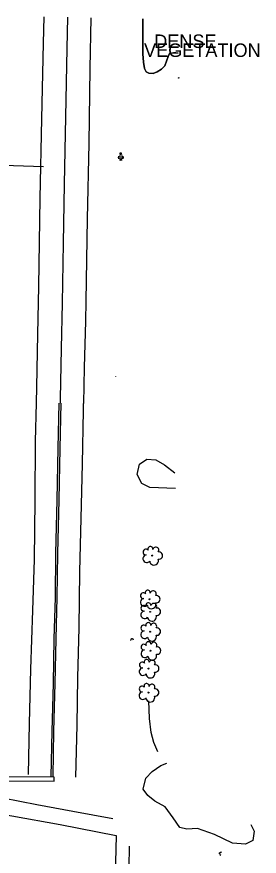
# Model space of a CAD drawing. Extents: x 2129547 to 2134906, y 657330 to 659734.
# Drawn here: x 2132484.8 to 2132610.2, y 659103.9 to 659538.9 of the extents above; entities that cross this region are included whole.
import ezdxf

# ---------------------------------------------------------------- set-up
doc = ezdxf.new("R2010")
doc.units = 0
for name, color, linetype in [('Default', 7, 'Continuous'), ('PM_X_CL_Double_Solid', 7, 'Continuous'), ('PM_X_CL_Double_Solid2', 7, 'Continuous'), ('PM_X_Crosswalk2', 7, 'Continuous'), ('PM_X_Lane_Line', 7, 'Continuous'), ('PM_X_Lane_Line2', 7, 'Continuous'), ('PM_X_Stop_Line2', 7, 'Continuous'), ('SN_X_Cantilever_Overhead', 7, 'Continuous'), ('UT_X_Electric_Cells', 7, 'Continuous'), ('UT_X_Misc_Cells', 7, 'Continuous'), ('UT_X_Unknown_Cells', 7, 'Continuous'), ('VG_X_Cells', 7, 'Continuous'), ('VG_X_Shrub_Line_Lt', 7, 'Continuous'), ('VG_X_Text', 7, 'Continuous'), ('VG_X_Tree_Line_Lt', 7, 'Continuous')]:
    doc.layers.add(name, color=color, linetype=linetype)

# ---------------------------------------------------------------- blocks, each defined once
blk = doc.blocks.new('DM')
at = {"layer": 'UT_X_Misc_Cells'}
blk.add_circle((0, 0), 0.00254, dxfattribs=at)
blk.add_arc((0.01016, 0), 0.01016, 90, 270, dxfattribs=at)
blk = doc.blocks.new('TREE')
at = {"layer": 'VG_X_Cells'}
blk.add_circle((0, 0), 0.00305, dxfattribs=at)
for centre, radius, start, end in [((-0.0125, 0.0428), 0.0167, 354.0047, 205.9741), ((0.0232, 0.0359), 0.0197, 323.83, 165.0376), ((-0.0362, -0.0197), 0.0251, 96.1722, 320.5737), ((-0.042, 0.0237), 0.0187, 39.0625, 279.5412), ((0.0439, 0.0005), 0.0243, 259.1453, 101.4596), ((0.012, -0.0331), 0.029, 184.9476, 19.4572)]:
    blk.add_arc(centre, radius, start, end, dxfattribs=at)
blk = doc.blocks.new('POINT_DISPLAY')
at = {"layer": 'Default'}
blk.add_line((0, 0), (0, 0), dxfattribs=at)

msp = doc.modelspace()

# ---------------------------------------------------------------- linework, layer by layer
at = {"layer": 'PM_X_CL_Double_Solid'}
msp.add_lwpolyline([(2132510.93, 659538.66), (2132510.63, 659522.52), (2132509.98, 659487.05), (2132509.34, 659452.23), (2132508.78, 659421.54), (2132508.27, 659390.56), (2132507.81, 659367.06), (2132507.25, 659340.87), (2132507.21, 659338.69)], dxfattribs=at)
at = {"layer": 'PM_X_CL_Double_Solid2'}
for points in [[(2132502.57, 659145.18), (2132503.03, 659168.68), (2132503.7, 659193.36), (2132504.11, 659216.62), (2132504.73, 659238), (2132505.03, 659260.78), (2132505.68, 659288.58), (2132506.27, 659315.28), (2132506.71, 659338.7)], [(2132503.57, 659145.16), (2132504.03, 659168.66), (2132504.7, 659193.34), (2132505.11, 659216.6), (2132505.72, 659237.98), (2132506.03, 659260.76), (2132506.68, 659288.55), (2132507.27, 659315.26), (2132507.71, 659338.68)]]:
    msp.add_lwpolyline(points, dxfattribs=at)
at = {"layer": 'PM_X_Crosswalk2'}
for points in [[(2132534.55, 659123.31), (2132513.69, 659127.04), (2132495.2, 659130.51), (2132477.48, 659133.95), (2132465.32, 659136.32)], [(2132469.3, 659081.92), (2132465.27, 659103.71), (2132460.59, 659128.44), (2132482.25, 659124.89), (2132507.25, 659120.29), (2132536.23, 659114.67), (2132535.64, 659093.84), (2132534.49, 659067.12), (2132533.02, 659033.77)], [(2132540.65, 659045.1), (2132541.37, 659064.12), (2132542.08, 659085.02), (2132542.85, 659098.09), (2132543.17, 659109.18)]]:
    msp.add_lwpolyline(points, dxfattribs=at)
at = {"layer": 'PM_X_Lane_Line'}
for points in [[(2132494.92, 659338.94), (2132495.11, 659346.96), (2132495.66, 659374.51), (2132496.16, 659399.15), (2132496.9, 659444.94), (2132497.82, 659486.1), (2132498.58, 659525.26), (2132498.94, 659538.9)], [(2132523.05, 659538.41), (2132522.63, 659512.16), (2132522.02, 659473.31), (2132521.15, 659434.29), (2132520.5, 659391.49), (2132520.3, 659381.16), (2132519.61, 659357.21), (2132519.32, 659338.44)]]:
    msp.add_lwpolyline(points, dxfattribs=at)
at = {"layer": 'PM_X_Lane_Line2'}
for points in [[(2132490.82, 659146.24), (2132491.44, 659172.61), (2132492.12, 659200.93), (2132493.01, 659231.29), (2132493.98, 659257.64), (2132494.29, 659288.48), (2132494.43, 659318.87), (2132494.92, 659338.94)], [(2132515.41, 659144.87), (2132516.03, 659171.87), (2132516.43, 659196.48), (2132516.99, 659222.22), (2132517.47, 659251.54), (2132518.16, 659278.93), (2132518.8, 659307.18), (2132519.26, 659334.82), (2132519.32, 659338.44)]]:
    msp.add_lwpolyline(points, dxfattribs=at)
at = {"layer": 'PM_X_Stop_Line2'}
msp.add_lwpolyline([(2132468.48, 659143.04), (2132504.1, 659142.84), (2132504.11, 659144.81), (2132468.49, 659145.01)], close=True, dxfattribs=at)
at = {"layer": 'SN_X_Cantilever_Overhead'}
msp.add_line((2132477.95, 659462.06), (2132498.68, 659461.4), dxfattribs=at)
at = {"layer": 'UT_X_Electric_Cells'}
for p, q in [((2132568.6, 659507.36), (2132568.52, 659507.06)), ((2132568.58, 659507.3), (2132568.64, 659507.3)), ((2132568.6, 659507.36), (2132568.64, 659507.36))]:
    msp.add_line(p, q, dxfattribs=at)
msp.add_circle((2132568.56, 659507.2), 0.065, dxfattribs=at)
msp.add_arc((2132568.64, 659507.33), 0.0319, 268.8767, 91.1233, dxfattribs=at)
at = {"layer": 'UT_X_Unknown_Cells'}
for p, q in [((2132539.2, 659468.01), (2132537.93, 659468.01)), ((2132538.56, 659467.37), (2132538.56, 659468.64)), ((2132538.02, 659466.83), (2132538.02, 659465.45)), ((2132539.11, 659466.83), (2132539.11, 659465.45)), ((2132535.85, 659352.48), (2132535.79, 659352.48)), ((2132535.79, 659352.43), (2132535.79, 659352.36)), ((2132535.82, 659352.45), (2132535.82, 659352.52)), ((2132535.85, 659352.43), (2132535.85, 659352.36))]:
    msp.add_line(p, q, dxfattribs=at)
for centre, radius, start, end in [((2132538.56, 659465.97), 1.4, 150.0184, 209.9816), ((2132538.56, 659465.97), 1.4, 60.0184, 120.0157), ((2132538.56, 659465.97), 1.4, 239.9843, 299.9816), ((2132538.56, 659465.71), 0.6, 205.1924, 334.8076), ((2132538.56, 659465.97), 1.4, 330.0184, 29.9816), ((2132535.82, 659352.38), 0.07, 150.0184, 209.9816), ((2132535.82, 659352.38), 0.07, 60.0184, 120.0157), ((2132535.82, 659352.37), 0.03, 205.1924, 334.8076), ((2132535.82, 659352.38), 0.07, 239.9843, 299.9816), ((2132535.82, 659352.38), 0.07, 330.0184, 29.9816)]:
    msp.add_arc(centre, radius, start, end, dxfattribs=at)
at = {"layer": 'VG_X_Shrub_Line_Lt'}
msp.add_lwpolyline([(2132557.82, 659157.97), (2132555.63, 659162.93), (2132554.28, 659168.11), (2132553.45, 659175.22), (2132553.09, 659184.52)], dxfattribs=at)
at = {"layer": 'VG_X_Text'}
msp.add_lwpolyline([(2132549.92, 659537.86), (2132549.94, 659529.59), (2132550.05, 659519.7), (2132550.32, 659515.32), (2132550.87, 659512.16), (2132551.64, 659510.35), (2132553.17, 659509.75), (2132555.3, 659509.51), (2132557.44, 659510.4), (2132559.65, 659511.69), (2132561.39, 659513.45), (2132563.11, 659518.24), (2132563.86, 659519.84), (2132565.81, 659520.23), (2132567.04, 659520.29), (2132568.32, 659520.08)], dxfattribs=at)
at = {"layer": 'VG_X_Tree_Line_Lt'}
for points in [[(2132568.32, 659520.08), (2132567.04, 659520.29), (2132565.81, 659520.23), (2132563.86, 659519.84), (2132563.11, 659518.24), (2132561.39, 659513.45), (2132559.65, 659511.69), (2132557.44, 659510.4), (2132555.3, 659509.51), (2132553.17, 659509.75), (2132551.64, 659510.35), (2132550.87, 659512.16), (2132550.32, 659515.32), (2132550.05, 659519.7), (2132549.94, 659529.59), (2132549.92, 659537.86)], [(2132566.92, 659294.5), (2132553.69, 659294.97), (2132549.48, 659296.99), (2132547.05, 659301.77), (2132548.22, 659307.02), (2132552.03, 659309.59), (2132556.74, 659309.35), (2132561.13, 659306.73), (2132566.54, 659302.63)], [(2132605.88, 659120.42), (2132607.62, 659116.9), (2132606.97, 659111.98), (2132603.19, 659110.22), (2132596.39, 659110.63), (2132587.14, 659115.25), (2132578.27, 659118.3), (2132572.68, 659117.86), (2132569.2, 659118.88), (2132565.63, 659123.73), (2132561.56, 659129.43), (2132556.14, 659132.39), (2132552.55, 659135.42), (2132550.16, 659138.73), (2132551.6, 659144.43), (2132554.88, 659147.81), (2132559.23, 659150.88), (2132562.47, 659152.1)]]:
    msp.add_lwpolyline(points, dxfattribs=at)

# ---------------------------------------------------------------- block references
at = {"layer": 'UT_X_Misc_Cells'}
for p, xscale, yscale, rotation in [((2132544.39, 659216.62), 78.74000000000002, 78.74000000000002, -86.24934655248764), ((2132589.72, 659105.42), 78.74000000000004, 78.74000000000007, -16.362187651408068)]:
    msp.add_blockref('DM', p, dxfattribs=dict(at, xscale=xscale, yscale=yscale, rotation=rotation))
at = {"layer": 'UT_X_Unknown_Cells', "xscale": 3.9370000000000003, "yscale": 3.9370000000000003}
msp.add_blockref('POINT_DISPLAY', (2132535.82, 659352.38), dxfattribs=at)
at = {"layer": 'VG_X_Cells', "xscale": 78.74000000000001, "yscale": 78.74000000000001}
for p in [(2132554.86, 659259.68), (2132553.52, 659237.05), (2132553.8, 659230.57), (2132553.78, 659220.27), (2132553.9, 659210.4), (2132552.97, 659201.16), (2132552.9, 659188.71)]:
    msp.add_blockref('TREE', p, dxfattribs=at)

# ---------------------------------------------------------------- texts
at = {"layer": 'VG_X_Text'}
for s, p in [('DENSE', (2132555.87, 659522.74)), ('VEGETATION', (2132550.62, 659518.08))]:
    msp.add_text(s, height=7, dxfattribs=at).set_placement(p)

doc.saveas('drawing.dxf')
